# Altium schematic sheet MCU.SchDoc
size A4; SheetNumber: 2; SheetTotal: 2
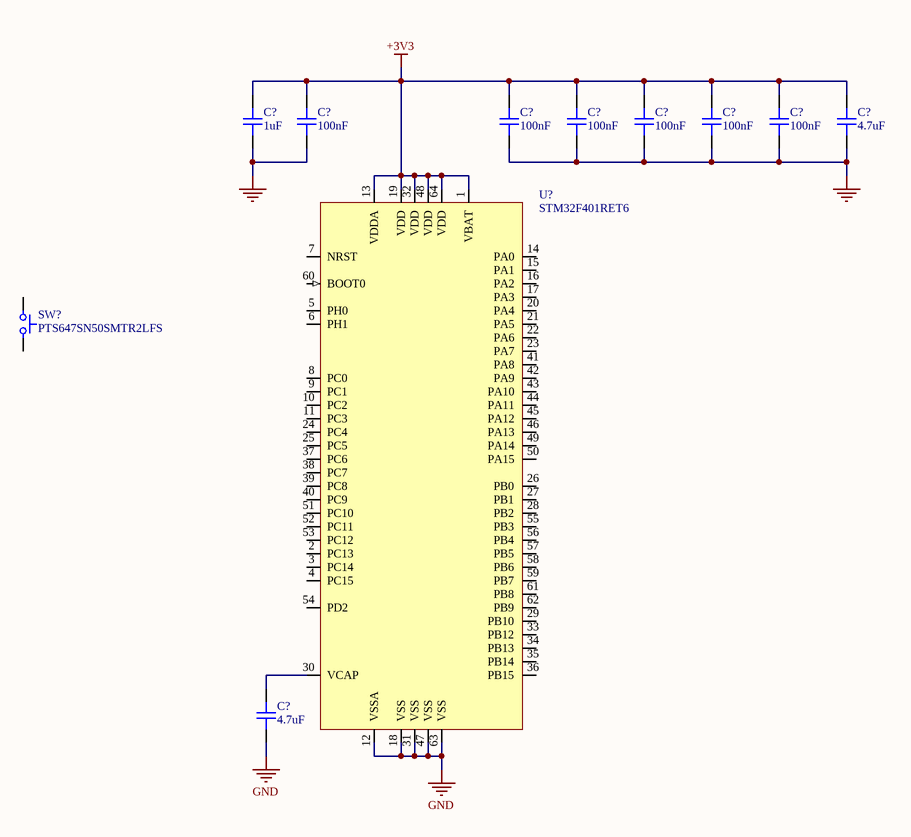
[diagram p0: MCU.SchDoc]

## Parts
(Parts that share a designator on the sheet are numbered #1, #2 ... from top to bottom, then left to right.)
C?#1  value 1uF  [CAP_0402_A]  (hidden comment: CC0402MRX5R6BB105)
C?#2  value 100nF  [CAP_0402_A]  (hidden comment: CC0402MRX5R6BB104)
C?#3  value 100nF  [CAP_0402_A]  (hidden comment: CC0402MRX5R6BB104)
C?#4  value 100nF  [CAP_0402_A]  (hidden comment: CC0402MRX5R6BB104)
C?#5  value 100nF  [CAP_0402_A]  (hidden comment: CC0402MRX5R6BB104)
C?#6  value 100nF  [CAP_0402_A]  (hidden comment: CC0402MRX5R6BB104)
C?#7  value 100nF  [CAP_0402_A]  (hidden comment: CC0402MRX5R6BB104)
C?#8  value 4.7uF  [CAP_0402_A]  (hidden comment: CC0402MRX5R6BB475)
C?#9  value 4.7uF  [CAP_0402_A]  (hidden comment: CC0402MRX5R6BB475)
SW?  PTS647SN50SMTR2LFS  [SW_TACTILE_SPST_NO_4.5mmX4.5mm]
U?  STM32F401RET6  [TSQFP50P1200X1200X160-64N]

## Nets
+3V3: C?#1.2 C?#2.2 C?#3.2 C?#4.2 C?#5.2 C?#6.2 C?#7.2 C?#8.2 U?.1(VBAT) U?.13(VDDA) U?.19(VDD) U?.32(VDD) U?.48(VDD) U?.64(VDD)
GND: C?#1.1 C?#2.1 C?#3.1 C?#4.1 C?#5.1 C?#6.1 C?#7.1 C?#8.1 C?#9.1 U?.12(VSSA) U?.18(VSS) U?.31(VSS) U?.47(VSS) U?.63(VSS)
NetC?#9_2: C?#9.2 U?.30(VCAP)

Not connected (* = marked no-connect by the designer): SW? 1 2; U? 2(PC13) 3(PC14) 4(PC15) 5(PH0) 6(PH1) 7(NRST) 8(PC0) 9(PC1) 10(PC2) 11(PC3) 14(PA0) 15(PA1) 16(PA2) 17(PA3) 20(PA4) 21(PA5) 22(PA6) 23(PA7) 24(PC4) 25(PC5) 26(PB0) 27(PB1) 28(PB2) 29(PB10) 33(PB12) 34(PB13) 35(PB14) 36(PB15) 37(PC6) 38(PC7) 39(PC8) 40(PC9) 41(PA8) 42(PA9) 43(PA10) 44(PA11) 45(PA12) 46(PA13) 49(PA14) 50(PA15) 51(PC10) 52(PC11) 53(PC12) 54(PD2) 55(PB3) 56(PB4) 57(PB5) 58(PB6) 59(PB7) 60(BOOT0) 61(PB8) 62(PB9)

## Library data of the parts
C?#1 = CMP-001-00016-4: Multilayer Ceramic Capacitor, 1 uF, 50 V, ± 10%, X5R, 0402 [1005 Metric]; Voltage Rating (DC): 10V; Tolerance: 20%; Temperature Coefficient: 30ppm/°C
C?#2-C?#7 = CMP-001-00009-5: Multilayer Ceramic Capacitor, 0.1 uF, 25 V, ± 20%, X7R, 0402 [1005 Metric]; Dielectric: X5R; Temperature Coefficient: 30ppm/°C; Voltage Rating: 10V
C?#8 C?#9 = CMP-001-00015-4: Multilayer Ceramic Capacitor, 4.7 uF, 50 V, ± 10%, X5R, 0402 [1005 Metric]; Tolerance: 20%; Temperature Coefficient: 30ppm/°C; Voltage Rating (DC): 10V
SW? = CMP-011-00000-2: Switch Tactile N.O. SPST Round Button Gull Wing 0.05A 12VDC 100000Cycles 0.98N SMD T/R; Ratings: IP40; Switch Function: Off-Mom; Illumination Type: Non-Illuminated; Actuator Type: Standard; Number of Positions: 2; Operating Force: 100gf; Switch Travel: 0.25mm
U? = CMP-020-00000-3: MCU 32-bit STM32 ARM Cortex M4 RISC 512KB Flash 1.8V/2.5V/3.3V 64-Pin LQFP Tray; Operating Supply Voltage: 3.3V; Peripherals: Brown-out Detect/Reset,POR,PWM,WDT,DMA; Nominal Supply Current: 1.8uA; Number of ADC Channels: 12; Interface: I2C,SPI,USB,IrDA,SDIO,UART,USART,LIN,I2S; Clock Frequency: 84MHz; Number of USB Channels: 1; Number of Timers/Counters: 8; Number of Channels: 16; Number of PWM Channels: 23; Number of UART Channels: 3; Number of Programmable I/O: 50; Watchdog Timer: Yes; Max Power Dissipation: 313mW; Min Supply Voltage: 1.7V; Data Bus Width: 32b; RAM Size: 96KB; Max Supply Voltage: 3.6V; Oscillator Type: Internal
